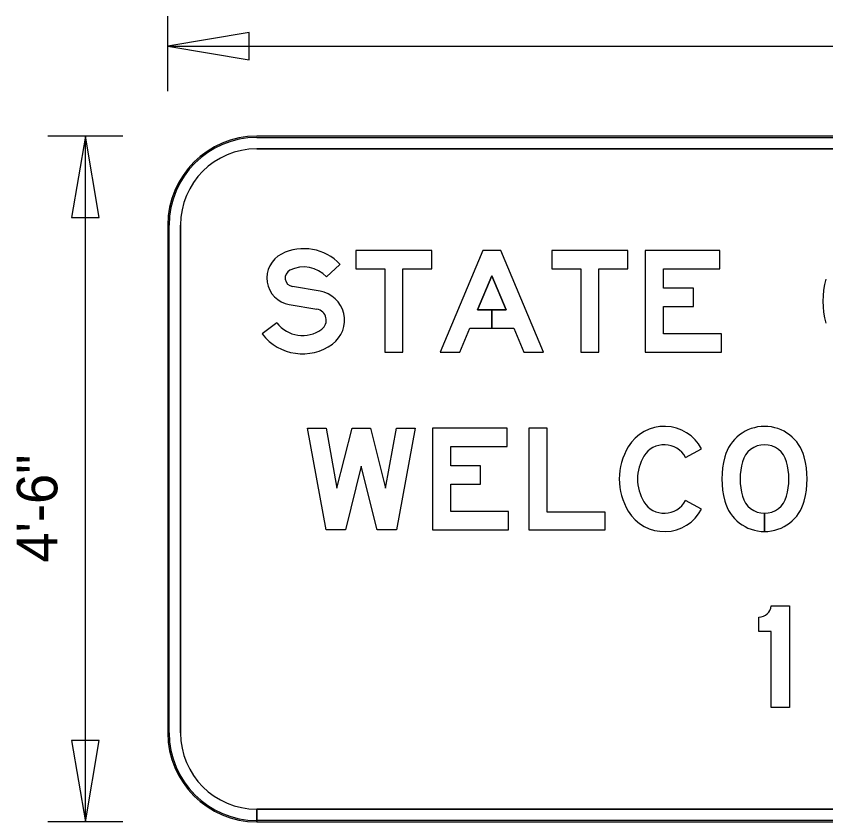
# Model space of a CAD drawing. Extents: x 0 to 770, y 0 to 495.
# Drawn here: x 48.4 to 118.2, y 230.7 to 300.2 of the extents above; entities that cross this region are included whole.
import ezdxf

# ---------------------------------------------------------------- set-up
doc = ezdxf.new("R2010")
doc.units = 0
for name, color, linetype in [('Default', 7, 'Continuous'), ('Dimension', 7, 'Continuous'), ('GSBWFill', 7, 'Continuous'), ('GSColorFill', 7, 'Continuous'), ('GSDims', 7, 'Continuous'), ('GSOutline', 7, 'Continuous')]:
    doc.layers.add(name, color=color, linetype=linetype)

msp = doc.modelspace()

# ---------------------------------------------------------------- linework, layer by layer
at = {"layer": 'Dimension'}
for points in [[(61.505, 297.566), (68.522, 296.377), (68.522, 298.755)], [(54.394, 289.809), (53.206, 282.792), (55.583, 282.792)], [(54.394, 230.705), (55.583, 237.722), (53.206, 237.722)]]:
    msp.add_lwpolyline(points, close=True, dxfattribs=at)
at = {"layer": 'GSBWFill'}
for p, q in [((198.319, 289.809), (69.167, 289.809)), ((198.319, 289.809), (69.167, 289.809)), ((69.167, 288.714), (198.319, 288.714)), ((61.505, 282.147), (61.505, 238.366)), ((61.505, 282.147), (61.505, 238.366)), ((62.6, 238.366), (62.6, 282.147)), ((75.192, 277.682), (76.347, 278.754)), ((74.625, 276.445), (72.239, 276.848)), ((71.976, 275.294), (74.362, 274.891)), ((70.897, 273.717), (69.649, 272.756)), ((106.127, 262.121), (107.519, 262.862)), ((107.519, 257.652), (106.127, 258.392)), ((106.127, 258.392), (106.127, 258.392)), ((112.947, 257.302), (112.947, 255.725)), ((112.948, 255.725), (112.948, 257.302)), ((69.167, 230.705), (69.167, 231.799)), ((198.319, 231.799), (69.178, 231.799)), ((69.178, 231.799), (69.178, 230.705)), ((69.167, 230.705), (198.319, 230.705)), ((69.178, 230.705), (198.319, 230.705))]:
    msp.add_line(p, q, dxfattribs=at)
for points in [[(77.704, 278.382), (80.2, 278.382), (80.2, 271.202), (81.776, 271.202), (81.776, 278.382), (84.271, 278.382), (84.271, 279.958), (77.704, 279.958)], [(90.667, 274.836), (89.438, 274.836), (89.438, 273.26), (91.329, 273.26), (92.194, 271.202), (93.903, 271.202), (90.225, 279.958), (88.649, 279.958), (84.972, 271.202), (86.681, 271.202), (87.545, 273.26), (89.437, 273.26), (89.437, 274.836), (88.207, 274.836), (89.437, 277.764)], [(94.603, 278.382), (97.099, 278.382), (97.099, 271.202), (98.675, 271.202), (98.675, 278.382), (101.17, 278.382), (101.17, 279.958), (94.603, 279.958)], [(109.226, 272.778), (104.235, 272.778), (104.235, 275.133), (106.818, 275.133), (106.818, 276.709), (104.235, 276.709), (104.235, 278.382), (109.095, 278.382), (109.095, 279.958), (102.659, 279.958), (102.659, 271.202), (109.226, 271.202)], [(78.186, 261.351), (76.807, 255.879), (75.143, 255.879), (73.545, 264.635), (75.147, 264.635), (76.088, 259.478), (77.388, 264.635), (78.984, 264.635), (80.283, 259.478), (81.224, 264.635), (82.827, 264.635), (81.229, 255.879), (79.565, 255.879)], [(90.882, 257.455), (85.891, 257.455), (85.891, 259.81), (88.474, 259.81), (88.474, 261.386), (85.891, 261.386), (85.891, 263.059), (90.751, 263.059), (90.751, 264.635), (84.315, 264.635), (84.315, 255.879), (90.882, 255.879)], [(99.2, 255.879), (99.2, 257.411), (94.209, 257.411), (94.209, 264.635), (92.633, 264.635), (92.633, 255.879)]]:
    msp.add_lwpolyline(points, close=True, dxfattribs=at)
for points in [[(113.517, 249.312), (115.093, 249.312), (115.093, 240.556)], [(115.093, 240.556), (113.517, 240.556), (113.517, 247.123), (112.466, 247.123), (112.466, 248.348)]]:
    msp.add_lwpolyline(points, dxfattribs=at)
for centre, radius, start, end in [((69.167, 282.147), 7.662, 90, 180), ((69.167, 282.147), 7.662, 90, 180), ((69.167, 282.147), 6.567, 90, 180), ((73.235, 275.864), 4.247, 42.87588, 116.91229), ((72.363, 277.582), 2.32, 116.91229, 260.40871), ((73.235, 275.864), 2.671, 42.87588, 116.91229), ((72.363, 277.582), 0.744, 116.91229, 260.40871), ((125.337, 275.58), 7.355, 165.03823, 194.96177), ((74.202, 273.941), 2.539, 306.12299, 80.40871), ((74.202, 273.941), 0.963, 306.12299, 80.40871), ((73.118, 275.427), 2.802, 217.58951, 306.12299), ((73.118, 275.427), 4.378, 217.5895, 306.12298), ((112.947, 261.24), 3.549, 14.96177, 165.03823), ((112.947, 261.24), 1.972, 14.96177, 165.03823), ((116.625, 260.257), 7.355, 165.03823, 194.96177), ((109.27, 260.257), 7.355, 345.03823, 14.96177), ((116.625, 260.257), 5.779, 165.03823, 194.96177), ((109.27, 260.257), 5.779, 345.03823, 14.96177), ((112.947, 259.274), 3.549, 194.96177, 270), ((112.947, 259.274), 1.972, 194.96177, 270), ((112.947, 259.274), 1.972, 270.01272, 345.03823), ((112.947, 259.274), 3.549, 270.00707, 345.03823), ((112.466, 249.403), 1.055, 270, 355.02089), ((69.167, 238.366), 7.662, 180, 270), ((69.167, 238.366), 7.662, 180, 270), ((69.167, 238.366), 6.567, 180, 270)]:
    msp.add_arc(centre, radius, start, end, dxfattribs=at)
for centre, major_axis, start_param, end_param in [((104.311, 261.154), (0, 3.634), 5.201543, 7.308565), ((104.311, 261.154), (0, 2.058), 5.201543, 7.308565), ((105.79, 260.257), (0, 5.364), 1.025379, 2.116213), ((105.79, 260.257), (0, 3.788), 1.025379, 2.116213), ((104.311, 259.359), (0, 2.058), 2.116213, 4.223235), ((104.311, 259.359), (0, 3.634), 2.116213, 4.223235)]:
    msp.add_ellipse(centre, major_axis=major_axis, ratio=0.999994, start_param=start_param, end_param=end_param, dxfattribs=at)
at = {"layer": 'GSColorFill'}
for p, q in [((198.319, 289.809), (69.167, 289.809)), ((198.319, 289.809), (69.167, 289.809)), ((198.319, 289.809), (69.167, 289.809)), ((69.167, 289.699), (198.319, 289.699)), ((69.167, 288.714), (198.319, 288.714)), ((61.505, 282.147), (61.505, 238.366)), ((61.505, 282.147), (61.505, 238.366)), ((61.505, 282.147), (61.505, 238.366)), ((61.615, 238.366), (61.615, 282.147)), ((62.6, 238.366), (62.6, 282.147)), ((75.192, 277.682), (76.347, 278.754)), ((74.625, 276.445), (72.239, 276.848)), ((71.976, 275.294), (74.362, 274.891)), ((70.897, 273.717), (69.649, 272.756)), ((106.127, 262.121), (107.519, 262.862)), ((107.519, 257.652), (106.127, 258.392)), ((106.127, 258.392), (106.127, 258.392)), ((112.947, 257.302), (112.947, 255.725)), ((112.948, 255.725), (112.948, 257.302)), ((69.167, 230.705), (69.167, 231.799)), ((198.319, 231.799), (69.178, 231.799)), ((69.178, 231.799), (69.178, 230.705)), ((69.167, 230.705), (69.167, 230.814)), ((69.167, 230.705), (198.319, 230.705)), ((198.319, 230.814), (69.168, 230.814)), ((69.168, 230.814), (69.168, 230.705)), ((69.168, 230.705), (198.319, 230.705)), ((69.178, 230.705), (198.319, 230.705))]:
    msp.add_line(p, q, dxfattribs=at)
for points in [[(77.704, 278.382), (80.2, 278.382), (80.2, 271.202), (81.776, 271.202), (81.776, 278.382), (84.271, 278.382), (84.271, 279.958), (77.704, 279.958)], [(90.667, 274.836), (89.438, 274.836), (89.438, 273.26), (91.329, 273.26), (92.194, 271.202), (93.903, 271.202), (90.225, 279.958), (88.649, 279.958), (84.972, 271.202), (86.681, 271.202), (87.545, 273.26), (89.437, 273.26), (89.437, 274.836), (88.207, 274.836), (89.437, 277.764)], [(94.603, 278.382), (97.099, 278.382), (97.099, 271.202), (98.675, 271.202), (98.675, 278.382), (101.17, 278.382), (101.17, 279.958), (94.603, 279.958)], [(109.226, 272.778), (104.235, 272.778), (104.235, 275.133), (106.818, 275.133), (106.818, 276.709), (104.235, 276.709), (104.235, 278.382), (109.095, 278.382), (109.095, 279.958), (102.659, 279.958), (102.659, 271.202), (109.226, 271.202)], [(78.186, 261.351), (76.807, 255.879), (75.143, 255.879), (73.545, 264.635), (75.147, 264.635), (76.088, 259.478), (77.388, 264.635), (78.984, 264.635), (80.283, 259.478), (81.224, 264.635), (82.827, 264.635), (81.229, 255.879), (79.565, 255.879)], [(90.882, 257.455), (85.891, 257.455), (85.891, 259.81), (88.474, 259.81), (88.474, 261.386), (85.891, 261.386), (85.891, 263.059), (90.751, 263.059), (90.751, 264.635), (84.315, 264.635), (84.315, 255.879), (90.882, 255.879)], [(99.2, 255.879), (99.2, 257.411), (94.209, 257.411), (94.209, 264.635), (92.633, 264.635), (92.633, 255.879)]]:
    msp.add_lwpolyline(points, close=True, dxfattribs=at)
for points in [[(113.517, 249.312), (115.093, 249.312), (115.093, 240.556)], [(115.093, 240.556), (113.517, 240.556), (113.517, 247.123), (112.466, 247.123), (112.466, 248.348)]]:
    msp.add_lwpolyline(points, dxfattribs=at)
for centre, radius, start, end in [((69.167, 282.147), 7.662, 90, 180), ((69.167, 282.147), 7.662, 90, 180), ((69.167, 282.147), 7.662, 90, 180), ((69.167, 282.147), 7.552, 90, 180), ((69.167, 282.147), 6.567, 90, 180), ((73.235, 275.864), 4.247, 42.87588, 116.91229), ((72.363, 277.582), 2.32, 116.91229, 260.40871), ((73.235, 275.864), 2.671, 42.87588, 116.91229), ((72.363, 277.582), 0.744, 116.91229, 260.40871), ((125.337, 275.58), 7.355, 165.03823, 194.96177), ((74.202, 273.941), 2.539, 306.12299, 80.40871), ((74.202, 273.941), 0.963, 306.12299, 80.40871), ((73.118, 275.427), 2.802, 217.58951, 306.12299), ((73.118, 275.427), 4.378, 217.5895, 306.12298), ((112.947, 261.24), 3.549, 14.96177, 165.03823), ((112.947, 261.24), 1.972, 14.96177, 165.03823), ((116.625, 260.257), 7.355, 165.03823, 194.96177), ((109.27, 260.257), 7.355, 345.03823, 14.96177), ((116.625, 260.257), 5.779, 165.03823, 194.96177), ((109.27, 260.257), 5.779, 345.03823, 14.96177), ((112.947, 259.274), 3.549, 194.96177, 270), ((112.947, 259.274), 1.972, 194.96177, 270), ((112.947, 259.274), 1.972, 270.01272, 345.03823), ((112.947, 259.274), 3.549, 270.00707, 345.03823), ((112.466, 249.403), 1.055, 270, 355.02089), ((69.167, 238.366), 7.662, 180, 270), ((69.167, 238.366), 7.662, 180, 270), ((69.167, 238.366), 7.662, 180, 270), ((69.167, 238.366), 7.552, 180, 270), ((69.167, 238.366), 6.567, 180, 270)]:
    msp.add_arc(centre, radius, start, end, dxfattribs=at)
for centre, major_axis, start_param, end_param in [((104.311, 261.154), (0, 3.634), 5.201543, 7.308565), ((104.311, 261.154), (0, 2.058), 5.201543, 7.308565), ((105.79, 260.257), (0, 5.364), 1.025379, 2.116213), ((105.79, 260.257), (0, 3.788), 1.025379, 2.116213), ((104.311, 259.359), (0, 2.058), 2.116213, 4.223235), ((104.311, 259.359), (0, 3.634), 2.116213, 4.223235)]:
    msp.add_ellipse(centre, major_axis=major_axis, ratio=0.999994, start_param=start_param, end_param=end_param, dxfattribs=at)
at = {"layer": 'GSDims'}
for p, q in [((61.505, 293.687), (61.505, 300.152)), ((61.505, 297.566), (205.981, 297.566)), ((57.627, 289.809), (51.162, 289.809)), ((54.394, 230.705), (54.394, 289.809)), ((57.627, 230.705), (51.162, 230.705))]:
    msp.add_line(p, q, dxfattribs=at)
at = {"layer": 'GSOutline'}
for p, q in [((198.319, 289.809), (69.167, 289.809)), ((198.319, 289.809), (69.167, 289.809)), ((198.319, 288.714), (69.167, 288.714)), ((61.505, 282.147), (61.505, 238.366)), ((61.505, 282.147), (61.505, 238.366)), ((62.6, 282.147), (62.6, 238.366)), ((75.192, 277.682), (76.347, 278.754)), ((74.625, 276.445), (72.239, 276.848)), ((71.976, 275.294), (74.362, 274.891)), ((70.897, 273.717), (69.649, 272.756)), ((106.127, 262.121), (107.519, 262.862)), ((107.519, 257.652), (106.127, 258.392)), ((106.127, 258.392), (106.127, 258.392)), ((69.167, 231.799), (198.319, 231.799)), ((69.167, 230.705), (198.319, 230.705)), ((69.167, 230.705), (198.319, 230.705))]:
    msp.add_line(p, q, dxfattribs=at)
for points in [[(77.704, 278.382), (80.2, 278.382), (80.2, 271.202), (81.776, 271.202), (81.776, 278.382), (84.271, 278.382), (84.271, 279.958), (77.704, 279.958)], [(87.545, 273.26), (91.329, 273.26), (92.194, 271.202), (93.903, 271.202), (90.225, 279.958), (88.649, 279.958), (84.972, 271.202), (86.681, 271.202)], [(94.603, 278.382), (97.099, 278.382), (97.099, 271.202), (98.675, 271.202), (98.675, 278.382), (101.17, 278.382), (101.17, 279.958), (94.603, 279.958)], [(109.226, 272.778), (104.235, 272.778), (104.235, 275.133), (106.818, 275.133), (106.818, 276.709), (104.235, 276.709), (104.235, 278.382), (109.095, 278.382), (109.095, 279.958), (102.659, 279.958), (102.659, 271.202), (109.226, 271.202)], [(90.667, 274.836), (89.437, 277.764), (88.207, 274.836)], [(78.186, 261.351), (76.807, 255.879), (75.143, 255.879), (73.545, 264.635), (75.147, 264.635), (76.088, 259.478), (77.388, 264.635), (78.984, 264.635), (80.283, 259.478), (81.224, 264.635), (82.827, 264.635), (81.229, 255.879), (79.565, 255.879)], [(90.882, 257.455), (85.891, 257.455), (85.891, 259.81), (88.474, 259.81), (88.474, 261.386), (85.891, 261.386), (85.891, 263.059), (90.751, 263.059), (90.751, 264.635), (84.315, 264.635), (84.315, 255.879), (90.882, 255.879)], [(99.2, 255.879), (99.2, 257.411), (94.209, 257.411), (94.209, 264.635), (92.633, 264.635), (92.633, 255.879)]]:
    msp.add_lwpolyline(points, close=True, dxfattribs=at)
for points in [[(113.517, 249.312), (115.093, 249.312), (115.093, 240.556)], [(115.093, 240.556), (113.517, 240.556), (113.517, 247.123), (112.466, 247.123), (112.466, 248.348)]]:
    msp.add_lwpolyline(points, dxfattribs=at)
for centre, radius, start, end in [((69.167, 282.147), 7.662, 90, 180), ((69.167, 282.147), 7.662, 90, 180), ((69.167, 282.147), 6.567, 90, 180), ((73.235, 275.864), 4.247, 42.87588, 116.91229), ((72.363, 277.582), 2.32, 116.91229, 260.40871), ((73.235, 275.864), 2.671, 42.87588, 116.91229), ((72.363, 277.582), 0.744, 116.91229, 260.40871), ((125.337, 275.58), 7.355, 165.03823, 194.96177), ((74.202, 273.941), 2.539, 306.12299, 80.40871), ((74.202, 273.941), 0.963, 306.12299, 80.40871), ((73.118, 275.427), 2.802, 217.58951, 306.12299), ((73.118, 275.427), 4.378, 217.5895, 306.12298), ((112.947, 261.24), 3.549, 14.96177, 165.03823), ((112.947, 261.24), 1.972, 14.96177, 165.03823), ((116.625, 260.257), 7.355, 165.03823, 194.96177), ((109.27, 260.257), 7.355, 345.03823, 14.96177), ((116.625, 260.257), 5.779, 165.03823, 194.96177), ((109.27, 260.257), 5.779, 345.03823, 14.96177), ((112.947, 259.274), 3.549, 194.96177, 345.03823), ((112.947, 259.274), 1.972, 194.96177, 345.03823), ((112.466, 249.403), 1.055, 270, 355.02089), ((69.167, 238.366), 7.662, 180, 270), ((69.167, 238.366), 7.662, 180, 270), ((69.167, 238.366), 6.567, 180, 270)]:
    msp.add_arc(centre, radius, start, end, dxfattribs=at)
for centre, major_axis, start_param, end_param in [((104.311, 261.154), (0, 3.634), 5.201543, 7.308565), ((104.311, 261.154), (0, 2.058), 5.201543, 7.308565), ((105.79, 260.257), (0, 5.364), 1.025379, 2.116213), ((105.79, 260.257), (0, 3.788), 1.025379, 2.116213), ((104.311, 259.359), (0, 2.058), 2.116213, 4.223235), ((104.311, 259.359), (0, 3.634), 2.116213, 4.223235)]:
    msp.add_ellipse(centre, major_axis=major_axis, ratio=0.999994, start_param=start_param, end_param=end_param, dxfattribs=at)

# ---------------------------------------------------------------- texts
at = {"layer": 'Default'}
msp.add_text('4\'-6"', height=3.5, rotation=90, dxfattribs=at).set_placement((51.982, 253.046))

doc.saveas('drawing.dxf')
